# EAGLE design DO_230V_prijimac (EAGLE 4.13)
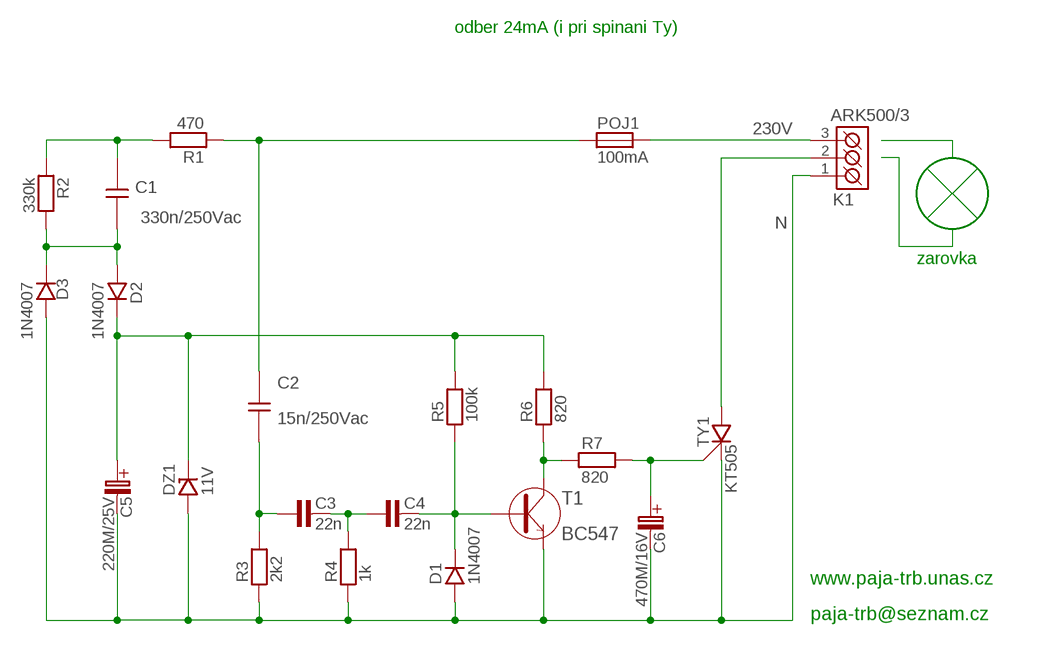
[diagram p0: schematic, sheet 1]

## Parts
C1  330n/250Vac  CFAC-22,5  [CFAC-22]
C2  15n/250Vac  CFAC-22,5  [CFAC-22]
C3  22n  C-KERAMIK_5  [C-5]
C4  22n  C-KERAMIK_5  [C-5]
C5  220M/25V  [C_EL_3,5]
C6  470M/16V  [C_EL_5]
D1  1N4007  1N4007_10  [D-10]
D2  1N4007  1N4007_10  [D-10]
D3  1N4007  1N4007_10  [D-10]
DZ1  11V  D-ZENEROVA_1,3W_BZX85V  [D-7,5]
K1  ARK500/3  [ARK500/3]
POJ1  100mA  PO_SHH  [POJ_SHH]
R1  470  R_7,5  [R-7,5]
R2  330k  R_7,5  [R-7,5]
R3  2k2  R_7,5  [R-7,5]
R4  1k  R_7,5  [R-7,5]
R5  100k  R_7,5  [R-7,5]
R6  820  R_7,5  [R-7,5]
R7  820  R_7,5  [R-7,5]
T1  BC547  BC546  [TO-92]
TY1  KT505  [TO-39]

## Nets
11V: C5.C+(C_EL+) D2.K DZ1.K R5.2 R6.2
230V: K1.3(K3) POJ1.P1
L: C2.2 POJ1.L1 R1.1
N: C5.C-(C_EL-) C6.C-(C_EL-) D1.A D3.A DZ1.A K1.1(K1) R3.1 R4.1 T1.3(E) TY1.1(K)
N$1: C2.1 C3.1 R3.2
N$3: C3.2 C4.1 R4.2
N$4: C4.2 D1.K R5.1 T1.2(B)
N$7: R6.1 R7.1 T1.1(C)
N$9: C6.C+(C_EL+) R7.2 TY1.2(G)
N$10: C1.1 R1.2 R2.1
N$11: C1.2 D2.A D3.K R2.2
ZATE: K1.2(K2) TY1.3(A)

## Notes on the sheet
- odber 24mA (i pri spinani Ty)
- zarovka
- www.paja-trb.unas.cz
- paja-trb@seznam.cz

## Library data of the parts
C1 C2 = #_GM99:CFAC-22,5
C3 C4 = #PaJa_20:C-KERAMIK: Kondenzator - keramicky
C5 = #PaJa_C-el:220M/25V
C6 = #PaJa_C-el:470M/16V
D1-D3 = #PaJa_20:1N4007: Usmernovaci dioda - 1A, 1000V
DZ1 = #PaJa_20:D-ZENEROVA: Zenerova dioda
K1 = #PaJa_20:ARK500/3: Svorkovnice - roztec 5mm - trojita
POJ1 = #PaJa_20:PO_SHH: Pojistkove pouzdro
R1-R7 = #PaJa_20:R: Rezistor
T1 = #PaJa_20:BC546: Tranzistor NPN - Univerzalni NF - Ic=0,1A
TY1 = #PaJa_20:KT505: Tyristor - TESLA - 400V, 1A

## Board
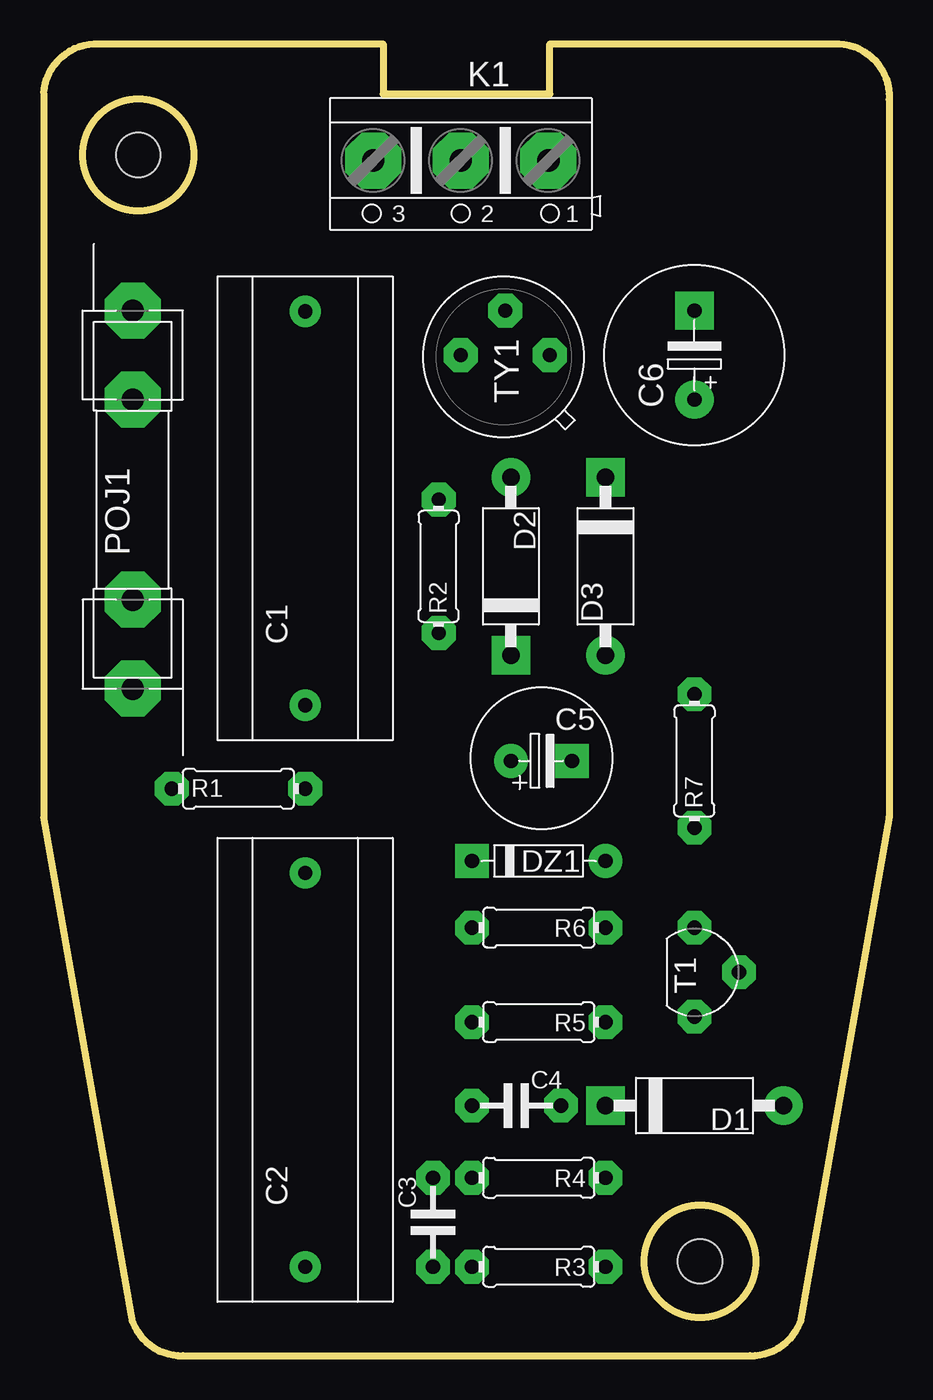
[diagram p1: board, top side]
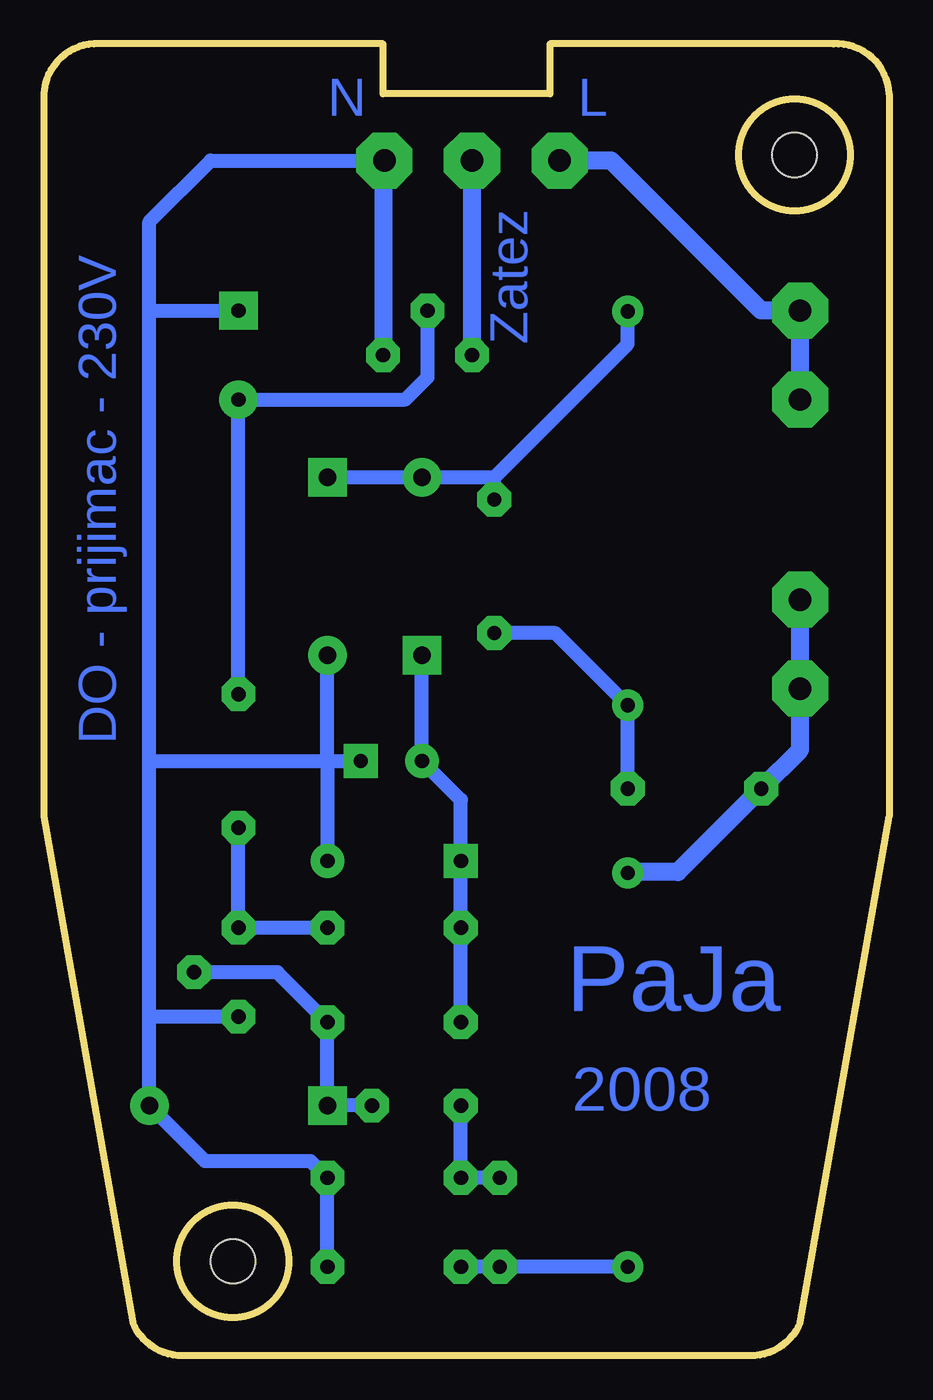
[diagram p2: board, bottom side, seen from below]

Size 48.26 x 74.93 mm. Coordinates in mm from the lower left corner, seen from the top.
Copper layers (1*16): Top 0.035mm / dielectric 1.5mm / Bottom 0.035mm
Design rules "default": minimum track width 10mil, minimum drill 24mil, track to track 8mil, track to pad 8mil, pad to pad 8mil, via to via 8mil, smd to smd 8mil, copper to edge 40mil, drill to drill 8mil, minimum pad ring 10mil, minimum via ring 8mil, stop-mask expansion 4mil, vias tented up to drill 0mil, thermal gap 10mil

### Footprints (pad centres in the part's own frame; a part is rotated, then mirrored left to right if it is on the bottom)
CFAC-22 = drill 0.813 pad 1.778 round: 1 0,0; 2 22.5,0
C-5 = drill 0.813 pad 1.93 octagon: 1 -2.54,0; 2 2.54,0
C_EL_3,5 = drill 0.813 pad 1.93 round: C+ 0,0 | drill 0.813 pad 1.93 square: C- 3.493,0
C_EL_5 = drill 0.813 pad 2.184 round: C+ -2.54,0 | drill 0.813 pad 2.184 square: C- 2.54,0
D-10 = drill 1.016 pad 2.184 round: A -5.08,0 | drill 1.016 pad 2.184 square: K 5.08,0
D-7,5 = drill 0.813 pad 1.93 round: A -3.81,0 | drill 0.813 pad 1.93 square: K 3.81,0
ARK500/3 = drill 1.27 pad 3.2 octagon: 1 -5,0; 2 0,0; 3 5,0
POJ_SHH = drill 1.27 pad 3.2 octagon: L1 -10.795,0; L2 -5.715,0; P1 10.795,0; P2 5.715,0
R-7,5 = drill 0.813 pad 1.93 octagon: 1 -3.81,0; 2 3.81,0
TO-92 = drill 0.813 pad 1.93 octagon: 1 0,2.54; 2 2.54,0; 3 0,-2.54
TO-39 = drill 0.813 pad 1.93 octagon: 1 0,2.54; 2 -2.54,0; 3 0,-2.54
U-KPZ3 = hole 2.54: 13.335,-25.4; -18.733,37.782

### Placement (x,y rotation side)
C1  14.92,37.15 90 top
C2  14.92,5.08 90 top
C3  22.22,7.62 90 top
C4  26.99,14.29 0 top
C5  26.67,33.97 0 top
C6  37.15,57.15 90 top
D1  37.15,14.29 180 top
D2  26.67,45.08 270 top
D3  32.07,45.08 90 top
DZ1  28.26,28.26 180 top
K1  23.81,68.26 180 top
POJ1  5.08,48.89 90 top
R1  11.11,32.38 0 top
R2  22.54,45.08 90 top
R3  28.26,5.08 180 top
R4  28.26,10.16 180 top
R5  28.26,19.05 180 top
R6  28.26,24.45 180 top
R7  37.15,33.97 90 top
T1  37.15,21.91 0 top
TY1  26.35,57.15 270 top
U$1  [U-KPZ3]  24.13,30.8 0 top

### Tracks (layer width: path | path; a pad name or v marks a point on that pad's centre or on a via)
11V
  Bottom 0.813: R5.2 R6.2 DZ1.K 24.45,31.75 C5.C+ D2.K
230V
  Bottom 1.016: K1.3 15.88,68.26 7.3,59.69 POJ1.P1 5.08,54.61
L
  Bottom 0.813: 14.92,27.62 C2.2
  Bottom 1.016: 5.08,43.18 POJ1.L1 5.08,34.61 R1.1 12.06,27.62 14.92,27.62
N
  Bottom 0.813: 42.23,19.37 D1.A 39.05,11.11 33.02,11.11 R4.1 R3.1 | 42.23,19.37 42.23,33.97 | 42.23,33.97 42.23,59.69 | 42.23,59.69 42.23,64.77 38.73,68.26 28.89,68.26 K1.1 | 42.23,19.37 T1.3 | 42.23,33.97 32.07,33.97 | 32.07,33.97 C5.C- | 32.07,33.97 D3.A | 32.07,33.97 DZ1.A | 42.23,59.69 C6.C-
  Bottom 1.016: 28.89,68.26 TY1.1
N$1
  Bottom 0.813: C2.1 C3.1 R3.2
N$3
  Bottom 0.813: C4.1 R4.2 C3.2
N$4
  Bottom 0.813: C4.2 D1.K R5.1 34.92,21.91 T1.2
N$7
  Bottom 0.813: R6.1 T1.1 R7.1
N$9
  Bottom 0.813: TY1.2 26.35,55.88 27.62,54.61 C6.C+ R7.2
N$10
  Bottom 0.813: R1.2 C1.1 19.05,41.27 R2.1
N$11
  Bottom 0.813: D3.K D2.A 22.54,50.16 | R2.2 22.54,50.16 | C1.2 14.92,57.78 22.54,50.16
ZATE
  Bottom 1.016: TY1.3 K1.2

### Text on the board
Bottom: L | N | Zatez | DO - prijimac - 230V | PaJa | 2008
